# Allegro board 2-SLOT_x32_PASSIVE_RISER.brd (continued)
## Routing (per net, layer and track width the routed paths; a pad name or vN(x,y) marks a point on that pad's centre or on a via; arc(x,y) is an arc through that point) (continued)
PE_CPU1_1C_RX_11_DP: length 65.7
  TOP w0.13: J1.178 46.53,3.99 46.28,4.24 46.28,4.85 46.96,8.23 49.09,10.36 50.82,10.7 52.53,12.41 55.35,12.97 55.99,13.61 55.99,14.55 55.05,16.43 55.05,19.1 55.99,20.98 55.99,21.58 56.47,22.06 67.21,24.2 68.55,25.54 85.49,28.93 87.91,31.35 88,32.31 88,32.54 v1(88.35,32.88)
  BOTTOM w0.13: J4.A35 87.51,36.18 87.57,36.01 87.78,35.91 87.99,35.7 87.99,33.24 v1(88.35,32.88)
PE_CPU1_1C_TX_8_DN: length 70.3
  L6 w0.135: v1(38.13,6.99) 38.5,6.62 38.97,6.62 39.19,6.84 39.65,9.11 43.54,13 43.7,13.8 43.7,14.49 42.77,16.34 42.77,19.19 43.7,21.04 43.7,21.73 44.94,22.97 53.01,24.59 54.01,25.59 65.27,27.84 66.6,29.17 75.83,31.02 76.12,31.3 76.12,31.51 76.41,31.79 76.61,31.79 77.7,32.88 77.7,35.27 76.7,36.27 76.7,40.05 76.95,40.3 77.16,40.4 77.22,40.58 J4.B46
  BOTTOM w0.13: J1.193 40.13,3.99 39.88,4.24 39.88,4.66 39.5,5.04 39.5,6.44 39.14,6.8 38.32,6.8 v1(38.13,6.99)
PE_CPU1_1C_TX_8_DP: length 70.4
  L6 w0.135: v1(38.13,5.97) 38.5,6.34 39.09,6.34 39.45,6.7 39.9,8.97 43.8,12.86 43.98,13.77 43.98,14.55 43.05,16.41 43.05,19.12 43.98,20.98 43.98,21.61 45.08,22.72 53.15,24.33 54.15,25.33 65.4,27.58 66.74,28.91 75.97,30.76 77.98,32.77 77.98,35.39 76.98,36.39 76.98,39.94 77.11,40.07 77.28,40.15 77.46,40.09 J4.B45
  BOTTOM w0.13: J1.195 39.33,3.99 39.58,4.24 39.58,4.53 39.19,4.92 39.19,5.3 39.02,5.47 39.02,5.86 39.19,6.04 39.19,6.31 39.01,6.49 38.27,6.49 38.13,6.35 v1(38.13,5.97)
PE_CPU1_1C_TX_9_DN: length 71.5
  L6 w0.135: v1(40.53,6.99) 40.9,6.62 41.37,6.62 41.59,6.84 41.97,8.72 46.14,12.89 47.1,13.08 47.7,13.68 47.7,14.49 46.77,16.34 46.77,19.19 47.71,21.05 47.71,21.72 48.42,22.43 53.72,23.49 54.7,24.47 54.78,24.49 65.87,26.71 67.21,28.05 79.36,30.48 79.65,30.76 79.65,30.97 79.93,31.26 80.14,31.26 81.7,32.82 81.7,35.27 80.7,36.27 80.7,40.03 80.95,40.28 81.16,40.39 81.22,40.57 J4.B42
  BOTTOM w0.13: v1(40.53,6.99) 40.72,6.8 41.54,6.8 41.9,6.44 41.9,5.04 42.28,4.66 42.28,4.24 42.53,3.99 J1.187
PE_CPU1_1C_TX_9_DP: length 71.5
  L6 w0.135: v1(40.53,5.97) 40.9,6.34 41.49,6.34 41.85,6.7 42.23,8.58 46.27,12.63 47.24,12.82 47.98,13.56 47.98,14.55 47.05,16.41 47.05,19.12 47.99,20.99 47.99,21.6 48.55,22.17 53.85,23.23 54.84,24.21 66.01,26.45 67.35,27.79 79.5,30.22 81.98,32.7 81.98,35.39 80.98,36.39 80.98,39.92 81.12,40.05 81.29,40.14 81.47,40.08 J4.B41
  BOTTOM w0.13: v1(40.53,5.97) 40.53,6.35 40.67,6.49 41.41,6.49 41.59,6.31 41.59,6.04 41.42,5.86 41.42,5.47 41.59,5.3 41.59,4.92 41.98,4.53 41.98,4.24 41.73,3.99 J1.189
PE_CPU1_1C_TX_10_DN: length 72.7
  L6 w0.135: J4.B38 85.22,40.57 85.16,40.39 84.95,40.29 84.7,40.04 84.7,36.27 85.7,35.27 85.7,33.01 83.34,30.65 83.14,30.65 82.85,30.37 82.85,30.16 82.57,29.88 67.82,26.93 66.46,25.56 65.49,25.41 55.36,23.38 54.51,22.54 52.13,22.06 51.7,21.63 51.7,21.04 50.77,19.19 50.77,16.34 51.7,14.49 51.7,13.74 50.42,12.46 47.8,11.94 44.32,8.45 43.99,6.84 43.77,6.62 43.3,6.62 v1(42.93,6.99)
  BOTTOM w0.13: J1.181 44.93,3.99 44.68,4.24 44.68,4.66 44.3,5.04 44.3,6.44 43.94,6.8 43.12,6.8 v1(42.93,6.99)
PE_CPU1_1C_TX_10_DP: length 72.7
  L6 w0.135: v1(42.93,5.97) 43.3,6.34 43.89,6.34 44.25,6.7 44.57,8.31 47.94,11.68 50.56,12.21 51.98,13.63 51.98,14.55 51.05,16.41 51.05,19.12 51.98,20.98 51.98,21.51 52.27,21.8 54.65,22.28 55.49,23.12 65.54,25.13 66.59,25.3 67.96,26.67 82.7,29.62 85.98,32.89 85.98,35.39 84.98,36.39 84.98,39.92 85.12,40.06 85.29,40.14 85.47,40.08 J4.B37
  BOTTOM w0.13: J1.183 44.13,3.99 44.38,4.24 44.38,4.53 43.99,4.92 43.99,5.3 43.82,5.47 43.82,5.86 43.99,6.04 43.99,6.31 43.81,6.49 43.07,6.49 42.93,6.35 v1(42.93,5.97)
PE_CPU1_1C_TX_11_DN: length 76
  L6 w0.135: J4.B34 89.22,40.58 89.4,40.52 89.63,40.64 90.39,40.64 90.98,40.05 90.98,36.27 89.98,35.27 89.98,32.45 86.71,29.17 84.47,28.73 68.5,25.53 67.16,24.19 56.47,22.06 55.99,21.58 55.99,20.99 55.05,19.12 55.05,16.41 55.98,14.55 55.98,13.64 55.3,12.96 52.53,12.41 50.82,10.7 49.04,10.35 46.96,8.27 46.65,6.7 46.29,6.34 45.7,6.34 v1(45.33,5.97)
  BOTTOM w0.13: v1(45.33,5.97) 45.33,6.35 45.47,6.49 46.21,6.49 46.39,6.31 46.39,6.04 46.22,5.86 46.22,5.47 46.39,5.3 46.39,4.92 46.78,4.53 46.78,4.24 46.53,3.99 J1.177
PE_CPU1_1C_TX_11_DP: length 76
  L6 w0.135: v1(45.33,6.99) 45.7,6.62 46.17,6.62 46.39,6.84 46.71,8.41 46.99,8.69 46.99,8.9 47.28,9.18 47.48,9.18 47.77,9.47 47.77,9.67 48.05,9.96 48.26,9.96 48.9,10.6 49.3,10.68 49.41,10.85 49.81,10.93 49.98,10.82 50.69,10.96 50.97,11.25 50.97,11.45 51.26,11.74 51.46,11.74 52.39,12.66 55.17,13.22 55.7,13.76 55.7,14.49 54.77,16.34 54.77,19.19 55.71,21.06 55.71,21.69 56.33,22.31 67.03,24.45 68.36,25.79 84.42,29 84.53,29.17 84.93,29.25 85.1,29.14 85.49,29.22 85.61,29.39 86,29.47 86.17,29.35 86.57,29.43 86.85,29.72 86.85,29.92 87.14,30.21 87.34,30.21 87.63,30.49 87.63,30.7 87.91,30.98 88.12,30.98 88.4,31.27 88.4,31.47 88.69,31.76 88.9,31.76 89.7,32.56 89.7,35.39 90.7,36.39 90.7,39.93 90.27,40.36 89.7,40.36 89.52,40.27 89.52,40.27 89.46,40.09 J4.B33
  BOTTOM w0.13: v1(45.33,6.99) 45.52,6.8 46.34,6.8 46.7,6.44 46.7,5.04 47.08,4.66 47.08,4.24 47.33,3.99 J1.175
PE_CPU1_1D_RX_12_DN: length 72.5
  TOP w0.13: J1.174 48.13,3.99 48.38,4.24 48.38,4.88 49.17,8.87 49.84,9.53 51.25,9.81 53.03,11.59 60.75,13.13 63.75,12.53 66.93,13.17 70.2,12.52 73.37,13.15 76.64,12.5 79.82,13.13 83.09,12.48 84.72,12.8 85.69,13.77 85.69,14.55 86.63,16.43 86.63,19.11 85.69,20.98 85.69,21.93 93.23,29.47 93.69,31.73 93.69,32.53 v1(93.33,32.88)
  BOTTOM w0.13: v1(93.33,32.88) 93.69,33.24 93.69,33.68 93.51,33.85 93.51,34.24 93.69,34.42 93.69,35.57 93.6,35.66 93.44,35.74 93.26,35.68 J4.A30
PE_CPU1_1D_RX_12_DP: length 72.5
  TOP w0.13: v1(94.35,32.88) 93.99,32.53 93.99,31.7 93.52,29.32 85.99,21.8 85.99,21.06 86.93,19.18 86.93,16.36 85.99,14.48 85.99,13.64 84.87,12.52 83.09,12.17 79.82,12.82 76.64,12.19 73.37,12.84 70.2,12.2 66.93,12.86 63.75,12.22 60.75,12.82 53.18,11.31 51.4,9.53 49.99,9.25 49.45,8.71 48.68,4.85 48.68,4.24 48.93,3.99 J1.172
  BOTTOM w0.13: v1(94.35,32.88) 93.99,33.24 93.99,35.7 93.78,35.91 93.57,36.01 93.51,36.18 J4.A29
PE_CPU1_1D_RX_13_DN: length 72.9
  TOP w0.13: v1(97.33,32.88) 97.7,32.51 97.7,32.33 97.6,31.84 87.69,21.93 87.69,20.98 88.63,19.11 88.63,16.43 87.69,14.55 87.69,13.77 85.69,11.77 83.08,11.25 79.81,11.9 76.63,11.27 73.36,11.92 70.19,11.28 66.92,11.94 63.74,11.3 60.75,11.9 53.64,10.48 51.46,8.3 50.78,4.88 50.78,4.24 50.53,3.99 J1.168
  BOTTOM w0.13: J4.A26 97.26,35.68 97.44,35.74 97.6,35.66 97.69,35.57 97.69,34.42 97.51,34.24 97.51,33.85 97.69,33.68 97.69,33.24 v1(97.33,32.88)
PE_CPU1_1D_RX_13_DP: length 72.9
  TOP w0.13: v1(98.35,32.88) 98,32.54 98,32.3 97.88,31.69 87.99,21.8 87.99,21.06 88.93,19.18 88.93,16.36 87.99,14.48 87.99,13.64 85.84,11.49 83.08,10.94 79.81,11.59 76.63,10.96 73.36,11.61 70.19,10.97 66.92,11.63 63.74,10.99 60.75,11.59 53.79,10.2 51.74,8.15 51.08,4.85 51.08,4.24 51.33,3.99 J1.166
  BOTTOM w0.13: v1(98.35,32.88) 97.99,33.24 97.99,35.7 97.78,35.91 97.57,36.01 97.51,36.18 J4.A25
PE_CPU1_1D_RX_14_DN: length 74.5
  TOP w0.13: v1(101.33,32.88) 101.7,32.52 101.7,32.13 101.58,31.55 98.06,28.03 95.23,27.47 89.69,21.93 89.69,20.98 90.63,19.11 90.63,16.43 89.69,14.55 89.69,13.77 86.6,10.68 83.17,10 79.9,10.65 76.72,10.02 73.45,10.67 70.28,10.04 67.01,10.69 63.83,10.05 60.75,10.67 55.06,9.53 53.87,8.34 53.18,4.88 53.18,4.24 52.93,3.99 J1.162
  BOTTOM w0.13: J4.A22 101.26,35.68 101.44,35.74 101.6,35.66 101.69,35.57 101.69,34.42 101.51,34.24 101.51,33.85 101.69,33.68 101.69,33.24 v1(101.33,32.88)
PE_CPU1_1D_RX_14_DP: length 74.5
  TOP w0.13: v1(102.35,32.88) 102,32.53 102,32.1 101.86,31.4 98.21,27.75 95.38,27.18 89.99,21.8 89.99,21.06 90.93,19.18 90.93,16.36 89.99,14.48 89.99,13.64 86.75,10.4 83.17,9.69 79.9,10.34 76.72,9.71 73.45,10.36 70.28,9.72 67.01,10.38 63.83,9.74 60.75,10.36 55.21,9.25 54.15,8.19 53.48,4.85 53.48,4.24 53.73,3.99 J1.160
  BOTTOM w0.13: J4.A21 101.52,36.18 101.57,36.01 101.78,35.91 101.99,35.7 101.99,33.24 v1(102.35,32.88)
PE_CPU1_1D_RX_15_DN: length 75.7
  TOP w0.13: v1(105.33,32.88) 105.69,32.53 105.69,32.08 105.4,31.79 103.49,31.41 99.01,26.92 96.16,26.35 91.69,21.88 91.69,20.98 92.63,19.1 92.63,16.43 91.69,14.55 91.69,13.74 87.6,9.66 83.16,8.77 79.89,9.42 76.72,8.79 73.44,9.44 70.27,8.8 67,9.46 63.82,8.82 60.75,9.44 56.76,8.64 56.22,8.1 55.58,4.88 55.58,4.24 55.33,3.99 J1.156
  BOTTOM w0.13: v1(105.33,32.88) 105.69,33.24 105.69,35.68 105.9,35.9 106.11,36 106.17,36.18 J4.A17
PE_CPU1_1D_RX_15_DP: length 75.7
  TOP w0.13: v1(106.35,32.88) 105.99,32.53 105.99,31.95 105.55,31.51 103.64,31.13 99.16,26.64 96.32,26.07 91.99,21.75 91.99,21.05 92.93,19.17 92.93,16.36 91.99,14.48 91.99,13.62 87.75,9.37 83.16,8.46 79.89,9.11 76.72,8.47 73.44,9.13 70.27,8.49 67,9.15 63.82,8.51 60.75,9.13 56.91,8.36 56.5,7.95 55.88,4.85 55.88,4.24 56.13,3.99 J1.154
  BOTTOM w0.13: J4.A16 106.42,35.67 106.25,35.73 106.08,35.65 105.99,35.56 105.99,34.42 106.17,34.24 106.17,33.85 105.99,33.68 105.99,33.24 v1(106.35,32.88)
PE_CPU1_1D_TX_12_DN: length 80.9
  L6 w0.135: v1(47.73,6.99) 48.1,6.62 48.57,6.62 48.79,6.84 49.2,8.9 49.8,9.5 51.26,9.79 53.04,11.57 60.75,13.11 63.75,12.51 66.92,13.14 70.19,12.49 73.37,13.12 76.64,12.47 79.81,13.11 83.08,12.45 84.72,12.78 85.7,13.76 85.7,14.55 86.63,16.41 86.63,19.12 85.71,20.95 85.71,21.91 93.84,30.04 93.84,30.24 94.13,30.53 94.33,30.53 95.7,31.9 95.7,35.27 94.7,36.27 94.7,40.05 94.95,40.3 95.16,40.4 95.22,40.58 J4.B28
  BOTTOM w0.13: J1.169 49.73,3.99 49.48,4.24 49.48,4.66 49.1,5.04 49.1,6.44 48.74,6.8 47.92,6.8 v1(47.73,6.99)
PE_CPU1_1D_TX_12_DP: length 80.9
  L6 w0.135: J4.B27 95.46,40.09 95.28,40.15 95.11,40.07 94.98,39.94 94.98,36.39 95.98,35.39 95.98,31.78 85.99,21.79 85.99,21.01 86.91,19.19 86.91,16.34 85.98,14.49 85.98,13.64 84.86,12.52 83.08,12.17 79.81,12.82 76.64,12.19 73.37,12.84 70.19,12.2 66.92,12.86 63.75,12.22 60.75,12.82 53.18,11.31 51.4,9.53 49.94,9.24 49.46,8.76 49.05,6.7 48.69,6.34 48.1,6.34 v1(47.73,5.97)
  BOTTOM w0.13: J1.171 48.93,3.99 49.18,4.24 49.18,4.53 48.79,4.92 48.79,5.3 48.62,5.47 48.62,5.86 48.79,6.04 48.79,6.31 48.61,6.49 47.87,6.49 47.73,6.35 v1(47.73,5.97)
PE_CPU1_1D_TX_13_DN: length 81.7
  L6 w0.135: v1(50.13,6.99) 50.5,6.62 50.97,6.62 51.19,6.84 51.49,8.33 53.61,10.45 60.82,11.89 63.81,11.29 66.92,11.91 70.19,11.26 73.36,11.89 76.63,11.24 79.81,11.87 83.08,11.22 85.73,11.75 87.7,13.72 87.7,14.55 88.63,16.41 88.63,19.12 87.7,20.98 87.7,21.85 95.95,30.1 97.28,30.37 98.46,31.54 98.46,31.75 98.74,32.03 98.95,32.03 99.7,32.79 99.7,35.27 98.7,36.27 98.7,40.05 98.94,40.3 99.16,40.4 99.22,40.58 J4.B24
  BOTTOM w0.13: J1.163 52.13,3.99 51.88,4.24 51.88,4.66 51.5,5.04 51.5,6.44 51.14,6.8 50.32,6.8 v1(50.13,6.99)
PE_CPU1_1D_TX_13_DP: length 81.7
  L6 w0.135: v1(50.13,5.97) 50.5,6.34 51.09,6.34 51.45,6.7 51.75,8.19 53.75,10.19 60.82,11.6 63.81,11.01 66.92,11.63 70.19,10.97 73.36,11.61 76.63,10.96 79.81,11.59 83.08,10.94 85.87,11.49 87.98,13.6 87.98,14.49 88.91,16.34 88.91,19.19 87.98,21.04 87.98,21.74 96.09,29.84 97.42,30.11 99.98,32.67 99.98,35.39 98.98,36.39 98.98,39.94 99.11,40.07 99.28,40.15 99.46,40.09 J4.B23
  BOTTOM w0.13: J1.165 51.33,3.99 51.58,4.24 51.58,4.53 51.19,4.92 51.19,5.3 51.02,5.47 51.02,5.86 51.19,6.04 51.19,6.31 51.01,6.49 50.27,6.49 50.13,6.35 v1(50.13,5.97)
PE_CPU1_1D_TX_14_DN: length 83.1
  L6 w0.135: J4.B20 103.22,40.58 103.16,40.4 102.95,40.3 102.7,40.05 102.7,36.27 103.7,35.27 103.7,32.85 102.47,31.62 102.26,31.62 101.98,31.33 101.98,31.13 100.68,29.83 96.92,29.07 89.7,21.85 89.7,20.98 90.63,19.12 90.63,16.41 89.7,14.55 89.7,13.72 86.65,10.67 83.23,9.98 79.96,10.64 76.79,10 73.52,10.66 70.34,10.02 67.07,10.68 63.9,10.04 60.82,10.66 55.09,9.51 53.89,8.31 53.59,6.84 53.37,6.62 52.9,6.62 v1(52.53,6.99)
  BOTTOM w0.13: J1.157 54.53,3.99 54.28,4.24 54.28,4.66 53.9,5.04 53.9,6.44 53.54,6.8 52.72,6.8 v1(52.53,6.99)
PE_CPU1_1D_TX_14_DP: length 83.2
  L6 w0.135: J4.B19 103.46,40.09 103.28,40.15 103.11,40.07 102.98,39.94 102.98,36.39 103.98,35.39 103.98,32.73 100.82,29.57 97.06,28.82 89.98,21.74 89.98,21.04 90.91,19.19 90.91,16.34 89.98,14.49 89.98,13.6 86.79,10.41 83.23,9.7 79.96,10.35 76.79,9.72 73.52,10.37 70.34,9.74 67.07,10.39 63.9,9.76 60.82,10.37 55.23,9.25 54.14,8.17 53.85,6.7 53.49,6.34 52.9,6.34 v1(52.53,5.97)
  BOTTOM w0.13: J1.159 53.73,3.99 53.98,4.24 53.98,4.53 53.59,4.92 53.59,5.3 53.42,5.47 53.42,5.86 53.59,6.04 53.59,6.31 53.41,6.49 52.67,6.49 52.53,6.35 v1(52.53,5.97)
PE_CPU1_1D_TX_15_DN: length 84.6
  L6 w0.135: J4.B15 108.23,40.12 108.41,40.18 108.54,40.11 108.7,39.95 108.7,36.85 107.7,34.85 107.7,33.02 106.87,32.2 106.67,32.2 106.38,31.91 106.38,31.71 106.1,31.42 105.89,31.42 105.61,31.14 105.61,30.93 105.32,30.65 105.12,30.65 104.83,30.36 104.83,30.16 104.55,29.87 104.34,29.87 104.06,29.59 104.06,29.38 103.83,29.16 97.8,27.95 91.7,21.85 91.7,20.98 92.63,19.12 92.63,16.41 91.7,14.55 91.7,13.72 87.61,9.63 83.22,8.75 79.95,9.41 76.78,8.77 73.51,9.43 70.34,8.79 67.06,9.45 63.89,8.81 60.77,9.44 58.9,9.06 58.73,9.17 58.33,9.1 58.22,8.93 57.82,8.85 57.65,8.96 57.26,8.88 57.14,8.71 56.75,8.63 56.25,8.14 55.99,6.84 55.77,6.62 55.3,6.62 v1(54.93,6.99)
  BOTTOM w0.13: J1.151 56.93,3.99 56.68,4.24 56.68,4.66 56.3,5.04 56.3,6.44 55.94,6.8 55.12,6.8 v1(54.93,6.99)
PE_CPU1_1D_TX_15_DP: length 84.6
  L6 w0.135: v1(54.93,5.97) 55.3,6.34 55.89,6.34 56.25,6.7 56.51,8 56.88,8.37 60.77,9.15 63.89,8.53 67.06,9.16 70.34,8.51 73.51,9.14 76.78,8.49 79.95,9.12 83.22,8.47 87.75,9.37 91.98,13.6 91.98,14.49 92.91,16.34 92.91,19.19 91.98,21.04 91.98,21.74 97.94,27.69 103.97,28.9 107.98,32.91 107.98,34.79 108.98,36.78 108.98,40.07 108.71,40.34 108.54,40.43 108.48,40.61 J4.B14
  BOTTOM w0.13: v1(54.93,5.97) 54.93,6.35 55.07,6.49 55.81,6.49 55.99,6.31 55.99,6.04 55.82,5.86 55.82,5.47 55.99,5.3 55.99,4.92 56.38,4.53 56.38,4.24 56.13,3.99 J1.153
PE_CPU1_2A_RX_0_DN: length 28.2
  TOP w0.13: v1(57.33,5.97) 57.33,6.35 57.47,6.49 57.82,6.49 57.98,6.34 57.98,5.66 57.8,5.48 57.8,5.09 57.98,4.92 57.98,4.24 57.73,3.99 J1.150
  L3 w0.135: J3.A81 42.2,15.79 42.14,15.61 41.93,15.5 41.7,15.27 41.7,13.66 46.06,9.3 49.5,8.61 51.63,9.04 52.65,9.24 55.51,8.67 55.77,8.4 55.89,7.8 55.89,6.63 56.18,6.34 56.96,6.34 v1(57.33,5.97)
PE_CPU1_2A_RX_0_DP: length 28.2
  TOP w0.13: v1(57.33,6.99) 57.52,6.8 57.95,6.8 58.28,6.47 58.28,4.24 58.53,3.99 J1.148
  L3 w0.135: v1(57.33,6.99) 56.96,6.62 56.3,6.62 56.17,6.74 56.17,7.83 56.03,8.54 55.64,8.93 55.25,9.01 55.13,9.18 54.74,9.26 54.57,9.14 52.65,9.53 52.25,9.45 52.08,9.56 51.69,9.48 51.57,9.31 49.5,8.9 46.19,9.56 45.08,10.67 45.08,10.88 44.8,11.16 44.59,11.16 44.31,11.45 44.31,11.65 44.02,11.94 43.82,11.94 43.53,12.22 43.53,12.43 43.24,12.71 43.04,12.71 42.75,13 42.75,13.2 42.47,13.49 42.26,13.49 41.98,13.77 41.98,15.15 42.1,15.27 42.27,15.36 42.45,15.3 J3.A80
PE_CPU1_2A_RX_1_DN: length 27.2
  TOP w0.13: J1.144 60.13,3.99 60.38,4.24 60.38,4.92 60.2,5.09 60.2,5.48 60.38,5.66 60.38,6.34 60.22,6.49 59.87,6.49 59.73,6.35 v1(59.73,5.97)
  L3 w0.135: v1(59.73,5.97) 59.36,6.34 58.58,6.34 58.29,6.63 58.29,7.8 58.21,8.21 57.5,8.93 56.8,9.62 52.55,10.47 50.64,10.09 49.32,9.82 48,10.09 46.25,11.84 45.9,12.19 45.7,13.21 45.7,15.27 45.93,15.5 46.14,15.61 46.2,15.79 J3.A77
PE_CPU1_2A_RX_1_DP: length 27.2
  TOP w0.13: v1(59.73,6.99) 59.92,6.8 60.35,6.8 60.68,6.47 60.68,4.24 60.93,3.99 J1.142
  L3 w0.135: J3.A76 46.45,15.3 46.27,15.36 46.1,15.27 45.98,15.16 45.98,13.24 46.16,12.32 46.45,12.04 46.65,12.04 46.94,11.75 46.94,11.55 47.22,11.26 47.43,11.26 47.71,10.98 47.71,10.77 48.14,10.35 49.32,10.11 49.9,10.23 50.01,10.4 50.41,10.47 50.58,10.36 52.55,10.76 54.68,10.33 54.85,10.44 55.24,10.36 55.36,10.19 55.75,10.11 55.93,10.23 56.32,10.15 56.43,9.98 56.94,9.88 57.69,9.12 57.9,9.12 58.18,8.84 58.18,8.63 58.47,8.35 58.57,7.83 58.57,6.74 58.7,6.62 59.36,6.62 v1(59.73,6.99)
PE_CPU1_2A_RX_2_DN: length 24.7
  TOP w0.13: v1(62.13,5.97) 62.13,6.35 62.27,6.49 62.62,6.49 62.78,6.34 62.78,5.66 62.6,5.48 62.6,5.09 62.78,4.92 62.78,4.24 62.53,3.99 J1.138
  L3 w0.135: J3.A73 50.2,15.79 50.14,15.61 49.93,15.51 49.7,15.28 49.7,13.66 51.29,12.07 58.59,10.61 60.57,8.63 60.69,8.03 60.69,6.63 60.98,6.34 61.76,6.34 v1(62.13,5.97)
PE_CPU1_2A_RX_2_DP: length 24.7
  TOP w0.13: J1.136 63.33,3.99 63.08,4.24 63.08,6.47 62.75,6.8 62.32,6.8 v1(62.13,6.99)
  L3 w0.135: v1(62.13,6.99) 61.76,6.62 61.1,6.62 60.97,6.74 60.97,8.06 60.96,8.15 60.83,8.77 60.28,9.32 60.28,9.52 60,9.81 59.79,9.81 59.51,10.09 59.51,10.3 59.22,10.58 59.01,10.58 58.73,10.87 58.33,10.95 58.22,11.12 57.82,11.2 57.65,11.08 53.58,11.9 53.46,12.07 53.07,12.15 52.9,12.03 52.5,12.11 52.39,12.28 51.99,12.36 51.82,12.25 51.43,12.33 50.75,13 50.75,13.2 50.47,13.49 50.26,13.49 49.98,13.78 49.98,15.16 50.09,15.28 50.27,15.36 50.45,15.3 J3.A72
PE_CPU1_2A_RX_3_DN: length 23.3
  TOP w0.13: J1.132 64.93,3.99 65.18,4.24 65.18,4.92 65,5.09 65,5.48 65.18,5.66 65.18,6.34 65.02,6.49 64.67,6.49 64.53,6.35 v1(64.53,5.97)
  L3 w0.135: v1(64.53,5.97) 64.16,6.34 63.38,6.34 63.09,6.63 63.09,7.8 62.85,9.02 60.54,11.32 54.99,12.44 53.7,13.72 53.7,15.28 53.93,15.51 54.14,15.61 54.2,15.79 J3.A69
PE_CPU1_2A_RX_3_DP: length 23.3
  TOP w0.13: v1(64.53,6.99) 64.72,6.8 65.15,6.8 65.48,6.47 65.48,4.24 65.73,3.99 J1.130
  L3 w0.135: J3.A68 54.45,15.3 54.27,15.36 54.09,15.28 53.98,15.16 53.98,13.84 54.26,13.55 54.47,13.55 54.75,13.27 54.75,13.06 55.12,12.69 55.52,12.61 55.69,12.73 56.09,12.65 56.2,12.48 56.6,12.4 56.77,12.51 57.16,12.43 57.28,12.26 57.67,12.18 57.84,12.3 58.24,12.22 58.35,12.05 60.68,11.58 61.56,10.71 61.76,10.71 62.05,10.42 62.05,10.22 62.33,9.93 62.54,9.93 62.82,9.65 62.82,9.44 63.11,9.16 63.37,7.83 63.37,6.74 63.5,6.62 64.16,6.62 v1(64.53,6.99)
PE_CPU1_2A_TX_0_DN: length 31.9
  BOTTOM w0.13: J1.145 59.33,3.99 59.08,4.24 59.08,4.85 58.82,6.13 58.96,6.34 58.89,6.72 58.68,6.86 58.6,7.24 58.74,7.44 58.66,7.83 58.46,7.96 58.38,8.34 58.03,8.69 54.72,9.35 51.55,8.72 47.99,9.43 45.68,11.74 45.68,11.99 45.41,12.26 45.16,12.26 44.89,12.54 44.89,12.79 44.61,13.06 44.36,13.06 44.09,13.34 43.99,13.82 43.99,14.55 42.99,16.55 42.99,19.58 43.47,20.06 44.01,20.06 44.17,19.97 44.23,19.8 J3.B79
PE_CPU1_2A_TX_0_DP: length 31.9
  BOTTOM w0.13: J3.B78 44.48,20.3 44.31,20.25 44.08,20.36 43.35,20.36 42.69,19.7 42.69,16.48 43.69,14.48 43.69,13.79 43.81,13.19 47.84,9.15 51.55,8.41 54.72,9.04 57.88,8.41 58.1,8.19 58.78,4.82 58.78,4.24 58.53,3.99 J1.147
PE_CPU1_2A_TX_1_DN: length 30.9
  BOTTOM w0.13: J1.139 61.73,3.99 61.48,4.24 61.48,5.16 61.21,6.49 61.35,6.69 61.27,7.07 61.07,7.21 60.99,7.59 61.13,7.8 61.05,8.18 60.85,8.32 60.77,8.7 59.9,9.57 54.78,10.59 51.64,9.96 50.51,10.19 49.87,10.83 49.87,11.08 49.59,11.35 49.34,11.35 49.07,11.63 49.07,11.88 48.8,12.15 48.55,12.15 48.27,12.43 47.99,13.83 47.99,14.55 46.99,16.55 46.99,19.57 47.47,20.04 48,20.04 48.17,19.96 48.22,19.79 J3.B75
PE_CPU1_2A_TX_1_DP: length 30.9
  BOTTOM w0.13: J1.141 60.93,3.99 61.18,4.24 61.18,5.12 60.49,8.55 59.75,9.28 54.78,10.28 51.64,9.65 50.36,9.91 47.99,12.28 47.69,13.8 47.69,14.48 46.69,16.48 46.69,19.7 47.34,20.35 48.07,20.35 48.3,20.24 48.48,20.29 J3.B74
PE_CPU1_2A_TX_2_DN: length 28.5
  BOTTOM w0.13: J1.133 64.13,3.99 63.88,4.24 63.88,5.34 63.63,6.61 63.76,6.82 63.69,7.2 63.48,7.34 63.4,7.72 63.54,7.93 63.47,8.31 63.26,8.44 63.18,8.83 61.54,10.46 55.59,11.66 55.45,11.86 55.07,11.94 54.87,11.8 54.48,11.88 54.35,12.08 53.97,12.16 53.76,12.02 53.38,12.1 52.08,13.4 51.99,13.82 51.99,14.55 50.99,16.55 50.99,19.58 51.47,20.06 52.01,20.06 52.17,19.97 52.23,19.8 J3.B71
PE_CPU1_2A_TX_2_DP: length 28.5
  BOTTOM w0.13: J3.B70 52.48,20.3 52.31,20.25 52.08,20.36 51.35,20.36 50.69,19.7 50.69,16.48 51.69,14.48 51.69,13.79 51.79,13.25 53.23,11.82 61.39,10.18 62.9,8.68 63.58,5.31 63.58,4.24 63.33,3.99 J1.135
PE_CPU1_2A_TX_3_DN: length 27.1
  BOTTOM w0.13: J1.127 66.53,3.99 66.28,4.24 66.28,5.34 65.99,6.79 66.13,7 66.05,7.38 65.84,7.52 65.77,7.9 65.91,8.1 65.83,8.49 65.62,8.62 65.55,9 63.2,11.36 59.01,12.19 58.88,12.4 58.49,12.47 58.29,12.34 57.91,12.41 57.77,12.62 57.39,12.7 57.18,12.56 56.8,12.63 56.09,13.35 55.99,13.82 55.99,14.55 54.99,16.55 54.99,19.58 55.47,20.06 56.01,20.06 56.17,19.97 56.23,19.8 J3.B67
PE_CPU1_2A_TX_3_DP: length 27.1
  BOTTOM w0.13: J3.B66 56.48,20.3 56.31,20.25 56.08,20.36 55.34,20.36 54.69,19.7 54.69,16.48 55.69,14.48 55.69,13.79 55.81,13.2 56.65,12.35 63.05,11.07 65.27,8.85 65.98,5.31 65.98,4.24 65.73,3.99 J1.129
PE_CPU1_2B_RX_4_DN: length 21.9
  TOP w0.13: v1(66.93,5.97) 66.93,6.35 67.07,6.49 67.42,6.49 67.58,6.34 67.58,5.66 67.4,5.48 67.4,5.09 67.58,4.92 67.58,4.24 67.33,3.99 J1.126
  L3 w0.135: v1(66.93,5.97) 66.56,6.34 65.78,6.34 65.49,6.63 65.49,7.8 65.25,9.03 62.03,12.25 58.38,12.98 57.7,13.66 57.7,15.27 57.93,15.5 58.14,15.61 58.2,15.79 J3.A65
PE_CPU1_2B_RX_4_DP: length 21.9
  TOP w0.13: J1.124 68.13,3.99 67.88,4.24 67.88,6.47 67.55,6.8 67.12,6.8 v1(66.93,6.99)
  L3 w0.135: v1(66.93,6.99) 66.56,6.62 65.9,6.62 65.77,6.74 65.77,7.83 65.5,9.17 65.22,9.46 65.22,9.66 64.93,9.95 64.73,9.95 64.44,10.23 64.44,10.44 64.16,10.72 63.95,10.72 63.67,11.01 63.67,11.21 63.38,11.5 63.18,11.5 62.17,12.51 61.74,12.59 61.63,12.77 61.23,12.84 61.06,12.73 60.67,12.81 60.55,12.98 60.16,13.06 59.99,12.95 59.59,13.02 59.48,13.2 59.08,13.27 58.91,13.16 58.51,13.24 57.98,13.78 57.98,15.15 58.1,15.27 58.27,15.36 58.45,15.3 J3.A64
PE_CPU1_2B_RX_5_DN: length 20.5
  TOP w0.13: J1.120 69.73,3.99 69.98,4.24 69.98,4.92 69.8,5.09 69.8,5.48 69.98,5.66 69.98,6.34 69.82,6.49 69.47,6.49 69.33,6.35 v1(69.33,5.97)
  L3 w0.135: v1(69.33,5.97) 68.96,6.34 68.18,6.34 67.89,6.63 67.89,7.39 67.48,9.47 64.13,12.82 62.22,13.2 61.7,13.72 61.7,15.27 61.93,15.5 62.14,15.61 62.2,15.79 J3.A61
PE_CPU1_2B_RX_5_DP: length 20.5
  TOP w0.13: J1.118 70.53,3.99 70.28,4.24 70.28,6.47 69.95,6.8 69.52,6.8 v1(69.33,6.99)
  L3 w0.135: J3.A60 62.45,15.3 62.27,15.36 62.1,15.28 61.98,15.16 61.98,13.84 62.36,13.46 62.76,13.38 62.93,13.49 63.32,13.41 63.44,13.24 64.26,13.08 64.63,12.71 64.84,12.71 65.12,12.43 65.12,12.22 65.41,11.94 65.61,11.94 65.9,11.65 65.9,11.45 66.18,11.16 66.39,11.16 66.67,10.87 66.67,10.67 66.96,10.38 67.16,10.38 67.45,10.1 67.45,9.89 67.73,9.61 67.96,8.49 68.13,8.38 68.21,7.98 68.09,7.81 68.17,7.42 68.17,6.74 68.3,6.62 68.96,6.62 v1(69.33,6.99)
PE_CPU1_2B_RX_6_DN: length 19.1
  TOP w0.13: J1.114 72.13,3.99 72.38,4.24 72.38,4.92 72.2,5.09 72.2,5.48 72.38,5.66 72.38,6.34 72.22,6.49 71.87,6.49 71.73,6.35 v1(71.73,5.97)
  L3 w0.135: v1(71.73,5.97) 71.36,6.34 70.58,6.34 70.29,6.63 70.29,7.8 69.96,9.49 65.7,13.74 65.7,15.27 65.93,15.5 66.14,15.61 66.2,15.79 J3.A57
PE_CPU1_2B_RX_6_DP: length 19
  TOP w0.13: v1(71.73,6.99) 71.92,6.8 72.35,6.8 72.68,6.47 72.68,4.24 72.93,3.99 J1.112
  L3 w0.135: J3.A56 66.45,15.3 66.27,15.36 66.1,15.27 65.98,15.16 65.98,13.86 66.26,13.58 66.47,13.58 66.76,13.29 66.76,13.08 67.04,12.8 67.25,12.8 67.53,12.51 67.53,12.31 67.82,12.02 68.02,12.02 68.31,11.74 68.31,11.53 68.59,11.25 68.8,11.25 69.08,10.96 69.08,10.76 69.37,10.47 69.57,10.47 69.86,10.19 69.86,9.98 70.21,9.63 70.36,8.91 70.53,8.79 70.61,8.4 70.49,8.23 70.57,7.83 70.57,6.74 70.7,6.62 71.36,6.62 v1(71.73,6.99)
PE_CPU1_2B_RX_7_DN: length 18.3
  TOP w0.13: J1.108 74.53,3.99 74.78,4.24 74.78,4.92 74.6,5.09 74.6,5.48 74.78,5.66 74.78,6.34 74.62,6.49 74.27,6.49 74.13,6.35 v1(74.13,5.97)
  L3 w0.135: J3.A53 70.16,15.87 70.1,15.69 69.89,15.58 69.7,15.39 69.7,13.84 70.08,11.93 70.92,11.1 70.92,11.1 72.31,9.71 72.69,7.77 72.69,6.57 73,6.26 73.84,6.26 v1(74.13,5.97)
PE_CPU1_2B_RX_7_DP: length 18.3
  TOP w0.13: J1.106 75.33,3.99 75.08,4.24 75.08,6.47 74.75,6.8 74.32,6.8 v1(74.13,6.99)
  L3 w0.135: v1(74.13,6.99) 73.68,6.54 73.12,6.54 72.97,6.69 72.97,7.8 72.78,8.77 72.89,8.94 72.81,9.34 72.64,9.45 72.56,9.85 71.89,10.52 71.89,10.72 71.6,11.01 71.4,11.01 71.11,11.29 71.11,11.5 70.83,11.79 70.62,11.79 70.34,12.07 70.19,12.79 70.31,12.96 70.23,13.36 70.06,13.47 69.98,13.87 69.98,15.28 70.06,15.35 70.23,15.44 70.41,15.38 J3.A52
PE_CPU1_2B_TX_4_DN: length 25.7
  BOTTOM w0.13: J1.121 68.93,3.99 68.68,4.24 68.68,5.34 68.36,6.97 68.49,7.17 68.42,7.55 68.21,7.69 68.13,8.07 68.27,8.28 68.19,8.66 67.99,8.8 67.91,9.18 64.82,12.27 62.59,12.71 62.45,12.92 62.07,13 61.86,12.86 61.48,12.94 61.34,13.14 60.96,13.22 60.75,13.08 60.37,13.16 60.06,13.47 59.99,13.82 59.99,14.55 58.99,16.55 58.99,19.57 59.47,20.05 60.01,20.05 60.17,19.97 60.23,19.79 J3.B63
PE_CPU1_2B_TX_4_DP: length 25.7
  BOTTOM w0.13: J1.123 68.13,3.99 68.38,4.24 68.38,5.31 67.63,9.03 64.67,11.99 60.22,12.88 59.78,13.32 59.69,13.79 59.69,14.48 58.69,16.48 58.69,19.7 59.34,20.35 60.08,20.35 60.31,20.24 60.48,20.3 J3.B62
PE_CPU1_2B_TX_5_DN: length 24
  BOTTOM w0.13: J1.115 71.33,3.99 71.08,4.24 71.08,5.34 70.78,6.82 70.92,7.03 70.85,7.41 70.64,7.55 70.56,7.93 70.7,8.13 70.62,8.52 70.42,8.65 70.34,9.03 67.75,11.63 67.75,11.88 67.47,12.15 67.22,12.15 66.95,12.43 66.95,12.67 66.67,12.95 66.43,12.95 66.15,13.22 64.24,13.61 63.99,13.85 63.99,14.55 62.99,16.55 62.99,19.57 63.47,20.05 64,20.05 64.17,19.96 64.23,19.79 J3.B59
PE_CPU1_2B_TX_5_DP: length 24
  BOTTOM w0.13: J3.B58 64.48,20.3 64.3,20.24 64.08,20.35 63.34,20.35 62.69,19.7 62.69,16.48 63.69,14.48 63.69,13.73 64.09,13.33 66,12.94 70.06,8.88 70.78,5.31 70.78,4.24 70.53,3.99 J1.117
PE_CPU1_2B_TX_6_DN: length 22.6
  BOTTOM w0.13: J1.109 73.73,3.99 73.48,4.24 73.48,5.34 73.26,6.44 73.4,6.64 73.32,7.03 73.12,7.16 73.04,7.54 73.18,7.75 73.1,8.13 72.89,8.27 72.82,8.65 69.67,11.79 69.67,12.04 69.4,12.32 69.15,12.32 68.88,12.59 68.88,12.84 68.6,13.11 68.35,13.11 68.08,13.39 67.99,13.82 67.99,14.55 66.99,16.55 66.99,19.57 67.47,20.04 68,20.04 68.17,19.96 68.22,19.79 J3.B55
PE_CPU1_2B_TX_6_DP: length 22.6
  BOTTOM w0.13: J1.111 72.93,3.99 73.18,4.24 73.18,5.31 72.54,8.5 67.8,13.24 67.69,13.79 67.69,14.48 66.69,16.48 66.69,19.7 67.34,20.35 68.07,20.35 68.3,20.23 68.48,20.29 J3.B54
PE_CPU1_2B_TX_7_DN: length 21.8
  BOTTOM w0.13: J3.B51 72.23,19.79 72.17,19.96 72,20.04 71.47,20.04 70.99,19.57 70.99,16.55 71.99,14.55 71.99,13.81 72.23,12.63 72.5,12.36 72.75,12.36 73.03,12.08 73.03,11.84 73.3,11.56 73.55,11.56 73.82,11.29 73.82,11.04 74.95,9.91 75.03,9.53 75.24,9.39 75.31,9.01 75.18,8.8 75.25,8.42 75.46,8.28 75.53,7.9 75.4,7.7 75.88,5.28 75.88,4.24 76.13,3.99 J1.103
PE_CPU1_2B_TX_7_DP: length 21.8
  BOTTOM w0.13: J1.105 75.33,3.99 75.58,4.24 75.58,5.25 74.67,9.76 71.95,12.48 71.69,13.78 71.69,14.48 70.69,16.48 70.69,19.7 71.34,20.35 72.08,20.35 72.3,20.24 72.48,20.29 J3.B50
PE_CPU1_2C_RX_8_DN: length 17
  TOP w0.13: v1(76.53,5.97) 76.53,6.35 76.67,6.49 77.02,6.49 77.18,6.34 77.18,5.66 77,5.48 77,5.09 77.18,4.92 77.18,4.24 76.93,3.99 J1.102
  L3 w0.135: J3.A48 75.21,15.26 75.39,15.32 75.56,15.24 75.71,15.09 75.71,13.67 75.63,13.27 74.81,9.2 75.09,7.8 75.09,6.63 75.38,6.34 76.16,6.34 v1(76.53,5.97)
PE_CPU1_2C_RX_8_DP: length 17
  TOP w0.13: v1(76.53,6.99) 76.72,6.8 77.15,6.8 77.48,6.47 77.48,4.24 77.73,3.99 J1.100
  L3 w0.135: J3.A47 75.46,15.75 75.52,15.57 75.73,15.47 75.99,15.21 75.99,13.65 75.9,13.21 76.01,13.04 75.93,12.65 75.76,12.53 75.43,10.87 75.1,9.2 75.37,7.83 75.37,6.74 75.5,6.62 76.16,6.62 v1(76.53,6.99)
PE_CPU1_2C_RX_9_DN: length 17.5
  TOP w0.13: v1(78.93,5.97) 78.93,6.35 79.07,6.49 79.42,6.49 79.58,6.34 79.58,5.66 79.4,5.48 79.4,5.09 79.58,4.92 79.58,4.24 79.33,3.99 J1.96
  L3 w0.135: J3.A44 79.21,15.26 79.39,15.32 79.56,15.24 79.7,15.1 79.7,13.78 79.34,11.97 78.07,10.7 77.49,7.83 77.49,6.63 77.78,6.34 78.56,6.34 v1(78.93,5.97)
PE_CPU1_2C_RX_9_DP: length 17.5
  TOP w0.13: J1.94 80.13,3.99 79.88,4.24 79.88,6.47 79.55,6.8 79.12,6.8 v1(78.93,6.99)
  L3 w0.135: J3.A43 79.46,15.75 79.52,15.57 79.73,15.47 79.98,15.21 79.98,13.76 79.9,13.36 80.01,13.19 79.94,12.79 79.76,12.68 79.6,11.84 78.33,10.57 77.77,7.8 77.77,6.74 77.9,6.62 78.56,6.62 v1(78.93,6.99)
PE_CPU1_2C_RX_10_DN: length 18.3
  TOP w0.13: J1.90 81.73,3.99 81.98,4.24 81.98,4.92 81.8,5.09 81.8,5.48 81.98,5.66 81.98,6.34 81.82,6.49 81.47,6.49 81.33,6.35 v1(81.33,5.97)
  L3 w0.135: v1(81.33,5.97) 80.96,6.34 80.18,6.34 79.89,6.63 79.89,7.83 80.17,9.23 83.48,12.53 83.7,13.65 83.7,15.1 83.56,15.24 83.39,15.32 83.21,15.26 J3.A40
PE_CPU1_2C_RX_10_DP: length 18.3
  TOP w0.13: v1(81.33,6.99) 81.52,6.8 81.95,6.8 82.28,6.47 82.28,4.24 82.53,3.99 J1.88
  L3 w0.135: J3.A39 83.46,15.75 83.52,15.57 83.73,15.47 83.98,15.22 83.98,13.62 83.73,12.39 83.45,12.11 83.45,11.9 83.16,11.62 82.96,11.62 80.43,9.09 80.17,7.8 80.17,6.74 80.3,6.62 80.96,6.62 v1(81.33,6.99)
PE_CPU1_2C_RX_11_DN: length 19.1
  TOP w0.13: J1.84 84.13,3.99 84.38,4.24 84.38,4.92 84.2,5.09 84.2,5.48 84.38,5.66 84.38,6.34 84.22,6.49 83.87,6.49 83.73,6.35 v1(83.73,5.97)
  L3 w0.135: v1(83.73,5.97) 83.36,6.34 82.58,6.34 82.29,6.63 82.29,7.72 82.43,8.38 87.7,13.66 87.7,15.1 87.57,15.24 87.4,15.32 87.21,15.26 J3.A36
PE_CPU1_2C_RX_11_DP: length 19.1
  TOP w0.13: v1(83.73,6.99) 83.92,6.8 84.35,6.8 84.68,6.47 84.68,4.24 84.93,3.99 J1.82
  L3 w0.135: v1(83.73,6.99) 83.36,6.62 82.7,6.62 82.57,6.74 82.57,7.69 82.68,8.25 87.2,12.77 87.41,12.77 87.7,13.05 87.7,13.26 87.98,13.54 87.98,15.22 87.73,15.47 87.52,15.57 87.46,15.75 J3.A35
PE_CPU1_2C_TX_8_DN: length 19.8
  BOTTOM w0.13: J3.B45 77.45,19.79 77.28,19.85 77.12,19.76 76.99,19.64 76.99,16.48 75.99,14.48 75.99,13.35 76.07,12.97 76.28,12.83 76.35,12.45 76.21,12.24 76.29,11.86 76.5,11.72 76.57,11.34 76.44,11.14 76.6,10.34 77.45,9.48 78.28,5.34 78.28,4.24 78.53,3.99 J1.97
PE_CPU1_2C_TX_8_DP: length 19.8
  BOTTOM w0.13: J3.B46 77.2,20.29 77.14,20.12 77.14,20.12 76.94,20.01 76.69,19.77 76.69,16.55 75.69,14.55 75.69,13.32 76.09,11.33 76.31,10.19 77.17,9.33 77.98,5.31 77.98,4.24 77.73,3.99 J1.99
PE_CPU1_2C_TX_9_DN: length 19.4
  BOTTOM w0.13: J1.91 80.93,3.99 80.68,4.24 80.68,5.34 80,8.75 80.23,9.93 80.44,10.07 80.52,10.45 80.38,10.66 80.46,11.04 80.21,12.25 80.35,12.45 80.27,12.83 80.07,12.97 79.99,13.35 79.99,14.48 80.99,16.48 80.99,19.64 81.12,19.76 81.28,19.85 81.28,19.85 81.45,19.79 J3.B41
PE_CPU1_2C_TX_9_DP: length 19.4
  BOTTOM w0.13: J1.93 80.13,3.99 80.38,4.24 80.38,5.31 79.69,8.75 79.94,9.99 80.14,11.04 79.69,13.32 79.69,14.55 80.69,16.55 80.69,19.77 80.94,20.01 81.13,20.11 81.14,20.12 81.2,20.29 J3.B42
PE_CPU1_2C_TX_10_DN: length 19.5
  BOTTOM w0.13: J3.B37 85.45,19.8 85.27,19.86 85.11,19.78 84.99,19.66 84.99,16.48 83.99,14.48 83.99,13.86 83.92,13.48 84.05,13.27 83.98,12.89 83.77,12.75 83.7,12.37 83.83,12.16 83.76,11.78 83.55,11.65 82.64,7.07 83.08,4.85 83.08,4.24 83.33,3.99 J1.85
PE_CPU1_2C_TX_10_DP: length 19.5
  BOTTOM w0.13: J1.87 82.53,3.99 82.78,4.24 82.78,4.82 82.32,7.07 83.69,13.89 83.69,14.55 84.69,16.55 84.69,19.78 84.93,20.03 85.14,20.13 85.14,20.13 85.2,20.3 J3.B38
PE_CPU1_2C_TX_11_DN: length 20.3
  BOTTOM w0.13: J3.B33 89.45,19.8 89.27,19.86 89.11,19.77 88.99,19.65 88.99,16.48 87.99,14.48 87.99,13.32 87.74,12.05 87.46,11.77 87.46,11.53 87.19,11.25 86.94,11.25 86.67,10.98 86.67,10.73 86.39,10.45 86.14,10.45 85.51,9.82 85,7.25 85.48,4.85 85.48,4.24 85.73,3.99 J1.79
PE_CPU1_2C_TX_11_DP: length 20.3
  BOTTOM w0.13: J1.81 84.93,3.99 85.18,4.24 85.18,4.82 84.69,7.25 85.23,9.97 87.46,12.2 87.69,13.35 87.69,14.55 88.69,16.55 88.69,19.78 88.93,20.02 89.14,20.13 89.14,20.13 89.2,20.3 J3.B34
PE_CPU1_2D_RX_12_DN: length 22.4
  TOP w0.13: v1(86.13,5.97) 86.13,6.35 86.27,6.49 86.62,6.49 86.78,6.34 86.78,5.66 86.6,5.48 86.6,5.09 86.78,4.92 86.78,4.24 86.53,3.99 J1.78
  L3 w0.135: J3.A30 93.21,15.26 93.39,15.32 93.56,15.23 93.7,15.1 93.7,13.71 92.63,12.64 88.2,11.75 84.8,8.34 84.69,7.83 84.69,6.63 84.98,6.34 85.76,6.34 v1(86.13,5.97)
PE_CPU1_2D_RX_12_DP: length 22.4
  TOP w0.13: J1.76 87.33,3.99 87.08,4.24 87.08,6.47 86.75,6.8 86.32,6.8 v1(86.13,6.99)
  L3 w0.135: v1(86.13,6.99) 85.76,6.62 85.1,6.62 84.97,6.74 84.97,7.8 85.05,8.2 88.34,11.49 91.69,12.16 91.86,12.05 92.26,12.13 92.37,12.3 92.77,12.38 93.98,13.59 93.98,15.21 93.73,15.46 93.52,15.57 93.46,15.75 J3.A29
PE_CPU1_2D_RX_13_DN: length 24
  TOP w0.13: v1(88.53,5.97) 88.53,6.35 88.67,6.49 89.02,6.49 89.18,6.34 89.18,5.66 89,5.48 89,5.09 89.18,4.92 89.18,4.24 88.93,3.99 J1.72
  L3 w0.135: v1(88.53,5.97) 88.16,6.34 87.38,6.34 87.09,6.63 87.09,7.83 87.22,8.46 89.14,10.38 95.77,11.71 97.7,13.64 97.7,15.1 97.56,15.23 97.39,15.32 97.21,15.26 J3.A26
PE_CPU1_2D_RX_13_DP: length 24
  TOP w0.13: v1(88.53,6.99) 88.72,6.8 89.15,6.8 89.48,6.47 89.48,4.24 89.73,3.99 J1.70
  L3 w0.135: J3.A25 97.46,15.75 97.52,15.57 97.73,15.46 97.98,15.21 97.98,13.53 97.7,13.24 97.7,13.04 97.41,12.75 97.21,12.75 95.91,11.45 89.28,10.12 87.48,8.33 87.37,7.8 87.37,6.74 87.5,6.62 88.16,6.62 v1(88.53,6.99)
PE_CPU1_2D_RX_14_DN: length 18.7
  TOP w0.13: v1(98.13,6.99) 97.94,6.79 96.82,6.79 96.38,6.35 96.38,4.24 96.13,3.99 J1.62
  L3 w0.135: J3.A22 101.27,15.37 101.45,15.43 101.6,15.36 101.7,15.25 101.7,13.61 101.62,13.21 101.45,13.1 101.37,12.7 101.49,12.53 101.37,11.96 101.09,11.68 100.88,11.68 100.6,11.39 100.6,11.19 99.79,10.39 99.72,9.99 99.55,9.88 99.47,9.48 99.58,9.31 99.5,8.91 99.33,8.8 99.25,8.4 99.36,8.23 99.24,7.59 99.24,6.66 99.1,6.53 98.58,6.53 v1(98.13,6.99)
PE_CPU1_2D_RX_14_DP: length 18.7
  TOP w0.13: J1.60 96.93,3.99 96.68,4.24 96.68,4.63 96.86,4.8 96.86,5.19 96.68,5.36 96.68,6.22 96.95,6.49 97.99,6.49 98.13,6.35 v1(98.13,5.97)
  L3 w0.135: v1(98.13,5.97) 98.41,6.25 99.22,6.25 99.51,6.55 99.51,7.56 100.05,10.25 101.63,11.82 101.9,13.16 101.98,13.58 101.98,15.37 101.76,15.59 101.57,15.68 101.51,15.86 J3.A21
PE_CPU1_2D_RX_15_DN: length 19.2
  TOP w0.13: v1(100.53,6.99) 100.34,6.79 99.22,6.79 98.78,6.35 98.78,4.24 98.53,3.99 J1.56
  L3 w0.135: J3.A17 106.22,15.75 106.16,15.57 105.95,15.46 105.7,15.21 105.7,13.82 105.41,13.54 105.21,13.54 104.92,13.25 104.92,13.05 102.18,10.3 101.68,7.83 101.68,6.74 101.56,6.62 100.9,6.62 v1(100.53,6.99)
PE_CPU1_2D_RX_15_DP: length 19.2
  TOP w0.13: v1(100.53,5.97) 100.53,6.35 100.39,6.49 99.35,6.49 99.08,6.22 99.08,5.36 99.26,5.19 99.26,4.8 99.08,4.63 99.08,4.24 99.33,3.99 J1.54
  L3 w0.135: J3.A16 106.47,15.26 106.29,15.32 106.12,15.23 105.98,15.09 105.98,13.71 102.44,10.16 101.96,7.8 101.96,6.63 101.67,6.34 100.9,6.34 v1(100.53,5.97)
PE_CPU1_2D_TX_12_DN: length 22.8
  BOTTOM w0.13: J1.73 88.13,3.99 87.88,4.24 87.88,4.85 87.41,7.21 87.74,8.88 90.1,11.24 90.35,11.24 90.62,11.52 90.62,11.76 90.9,12.04 92.01,12.26 92.21,12.12 92.6,12.2 92.73,12.41 93.11,12.48 93.87,13.24 93.99,13.84 93.99,14.48 94.99,16.48 94.99,19.65 95.11,19.77 95.28,19.85 95.45,19.79 J3.B27
PE_CPU1_2D_TX_12_DP: length 22.8
  BOTTOM w0.13: J3.B28 95.2,20.3 95.14,20.12 95.14,20.12 94.93,20.02 94.69,19.77 94.69,16.55 93.69,14.55 93.69,13.87 93.59,13.39 92.96,12.76 90.75,12.32 87.46,9.03 87.1,7.21 87.58,4.82 87.58,4.24 87.33,3.99 J1.75
PE_CPU1_2D_TX_13_DN: length 24.1
  BOTTOM w0.13: J3.B23 99.45,19.79 99.28,19.85 99.11,19.77 98.99,19.65 98.99,16.48 97.99,14.48 97.99,13.84 97.85,13.14 97.58,12.86 97.58,12.62 97.3,12.34 97.05,12.34 96.13,11.42 95.75,11.34 95.61,11.13 95.23,11.06 95.02,11.2 92.39,10.67 90.07,8.34 89.82,7.13 90.28,4.85 90.28,4.24 90.53,3.99 J1.67
PE_CPU1_2D_TX_13_DP: length 24.1
  BOTTOM w0.13: J3.B24 99.2,20.3 99.14,20.12 99.14,20.12 98.93,20.02 98.69,19.77 98.69,16.55 97.69,14.55 97.69,13.87 97.57,13.29 95.98,11.7 92.24,10.95 89.78,8.49 89.51,7.13 89.98,4.82 89.98,4.24 89.73,3.99 J1.69
PE_CPU1_2D_TX_14_DN: length 21.2
  BOTTOM w0.13: J3.B19 103.45,19.79 103.28,19.85 103.12,19.76 102.99,19.64 102.99,16.48 101.99,14.48 101.99,13.89 101.82,13.04 101.55,12.77 101.55,12.52 101.27,12.24 101.03,12.24 100.75,11.97 100.75,11.72 100.48,11.45 100.23,11.45 97.28,8.5 97.01,7.17 97.48,4.85 97.48,4.24 97.73,3.99 J1.57
PE_CPU1_2D_TX_14_DP: length 21.3
  BOTTOM w0.13: J1.59 96.93,3.99 97.18,4.24 97.18,4.82 96.7,7.17 97,8.65 101.54,13.19 101.69,13.92 101.69,14.55 102.69,16.55 102.69,19.77 102.94,20.01 103.14,20.12 103.14,20.12 103.2,20.29 J3.B20
PE_CPU1_2D_TX_15_DN: length 24.1
  BOTTOM w0.13: J1.51 100.13,3.99 99.88,4.24 99.88,4.85 99.42,7.17 99.68,8.48 103.77,12.57 103.99,13.69 103.99,14.48 104.99,16.48 104.99,17.04 105.26,17.31 108.56,17.97 108.99,18.39 108.99,19.77 108.72,20.04 108.54,20.13 108.48,20.3 J3.B14
PE_CPU1_2D_TX_15_DP: length 24.1
  BOTTOM w0.13: J3.B15 108.23,19.8 108.41,19.86 108.54,19.79 108.69,19.64 108.69,18.52 108.41,18.25 105.11,17.59 104.69,17.16 104.69,16.55 103.69,14.55 103.69,13.72 103.49,12.72 103.21,12.45 102.96,12.45 102.69,12.17 102.69,11.92 102.42,11.65 102.17,11.65 101.89,11.37 101.89,11.13 99.4,8.63 99.1,7.17 99.58,4.82 99.58,4.24 99.33,3.99 J1.53
PWRBRK_J3_N: length 25.1
  TOP w0.114: U1.6 103.89,10.41 104.51,9.79 104.51,9 104.65,8.86 R99.1 105.16,8.44 104.08,7.37 102.36,7.37 100.71,9.02 99.57,9.02 95.76,12.83 95.76,14.86 94.87,15.74 94.87,18.52 94.8,18.59 94.8,19.5 94.11,20.19 93.66,20.19 J3.B30
PWRBRK_J4_N: length 53.1
  TOP w0.114: U1.4 102.59,10.38 102.23,10.03 R98.1 100.09,9.64 99.69,10.03 99.69,14.99 100.71,16 100.71,18.03 100.87,18.2 100.87,19.34 101.81,20.27 101.81,27.64 104.51,30.34 105.72,30.34 107.7,32.32 107.7,35.44 107.27,35.87 107.26,35.87 106.93,36.2 106.93,37.21 106.17,37.97 93.47,37.97 92.84,38.6 J4.B30
PWRBRK_SLOT4_N: length 19.8
  TOP w0.114: v1(106.05,12.19) 105.26,12.98 R74.2 104.42,12.98 104.27,12.83 U1.1 103.89,12.19 103.76,12.06 102.7,12.06 102.59,12.18 U1.3 ; v1(113.6,5.08) 113.6,4.63 112.93,3.96 J1.20
  L3 w0.137: v1(106.05,12.19) 110.24,8 112.65,8 113.15,7.5 113.15,5.78 113.16,5.78 113.16,5.52 v1(113.6,5.08)
RST_J3_N: length 2.5
  TOP w0.114: R26.2 110.26,8.53 110.49,8.77 U6.2 110.49,10.41 v1(110.49,10.41)
RST_J3_TRI_N: length 6.4
  TOP w0.114: U6.4 111.58,11.49 111.71,11.62 111.71,12.03 111.72,12.04 111.72,12.63 111.71,12.63 111.71,13.92 113.03,15.24 113.03,15.71 J3.A11
RST_J4_N: length 1.6
  TOP w0.114: R52.2 v1(111,30.61) 111.38,30.99 U7.2
RST_J4_TRI_N: length 4.3
  TOP w0.114: U7.4 112.03,34.43 113.84,36.24 J4.A11
RST_N: length 3.7
  TOP w0.114: R112.1 95.25,57.61 94.99,57.35 v1(94.99,56.21) U2.3
RST_P1_SLOT4_N: length 34.4
  TOP w0.114: v1(110.49,11.68) 110.49,11.18 110.24,10.92 109.22,10.92 108.93,10.64 108.93,7.91 109.12,7.72 R26.1 109.73,7.24 109.22,6.73 v1(108.71,6.73) ; v1(111.32,22.73) 111.32,25.08 110.74,25.65 110.74,27.18 111,27.43 R52.1
  L3 w0.137: v1(110.49,11.68) 111.7,11.68 111.89,11.87 111.89,13.97 113.54,15.62 114.17,15.62 114.63,16.08 114.63,19.57 113.67,20.54 113.67,20.95 111.89,22.73 v1(111.32,22.73)
  BOTTOM w0.114: J1.29 108.93,6.52 v1(108.71,6.73)
SLOT4_PRSNT_R_N: length 7.3
  TOP w0.114: R29.2 v1(37.32,8.86)
  BOTTOM w0.114: J1.199 37.73,4.56 37.55,4.74 37.55,8.63 v1(37.32,8.86)
SLOT4_WAKE_R_N: length 36.3
  TOP w0.114: v1(112.39,10.9) 112.08,10.9 111.95,10.77 111.95,8.06 111.61,7.72 R1.1 110.72,7.72 109.47,6.48 109.47,4.32 109.73,4.06 J1.28 ; v1(112.59,22.73) 112.59,24.32 111.25,25.65 111.25,27.05 111.44,27.24 111.44,29.88 113.28,31.72 R54.1
  L3 w0.137: v1(112.39,10.9) 112.39,13.84 113.79,15.24 114.43,15.24 115.06,15.88 115.06,19.72 114.05,20.73 114.05,21.27 v1(112.59,22.73)
SMB_0_ISO_SCL: length 22
  TOP w0.114: Q1.2 104.72,45.9 105.18,45.44 R102.1 R59.2 v1(106.15,44.3)
  L3 w0.137: v1(106.15,44.3) 106.82,43.62 116.91,43.62 117.98,42.55 117.98,40.89 118.62,40.26 118.92,40.26 J4.B5
SMB_0_ISO_SDA: length 16.2
  TOP w0.114: v1(109.7,44.3) R60.2 R103.1 108.74,45.44 108.28,45.9 Q2.2
  L3 w0.137: v1(109.7,44.3) 109.91,44.09 117.1,44.09 118.84,42.35 J4.B6
SMB_0_R_SCL: length 34.5
  TOP w0.114: v1(105.68,46.89) Q1.3 106.81,46.1 106.96,45.95 R59.1 ; R108.1 v1(93.22,60.58) R33.2
  L3 w0.137: v1(93.22,60.58) 93.47,60.83 93.47,61.37 93.91,61.81 98.87,61.81 104.61,56.07 104.61,46.4 105.16,45.85 106.91,45.85 107.23,46.17 107.23,46.7 107.04,46.89 v1(105.68,46.89)
SMB_0_R_SDA: length 34.5
  TOP w0.114: v1(109.23,46.89) Q2.3 110.24,46.1 110.52,45.82 R60.1 ; R109.1 v1(94.23,60.58) R32.2
  L3 w0.137: v1(109.23,46.89) 107.85,46.89 107.7,46.74 107.7,45.97 107.1,45.38 104.96,45.38 104.14,46.2 104.14,55.88 98.68,61.34 94.11,61.34 93.94,61.17 93.94,60.87 v1(94.23,60.58)
SMB_0_SCL: length 3.8
  TOP w0.114: R33.1 93.22,57.66 93.69,57.19 v1(93.69,56.21) U2.5
SMB_0_SDA: length 3.6
  TOP w0.114: R32.1 v1(94.23,57.78) 94.34,57.68 U2.4
SMB_1_ISO_SCL: length 21.8
  TOP w0.114: v1(106.15,23.98) R62.2 R101.1 105.18,25.12 104.72,25.58 Q4.2
  L3 w0.137: v1(106.15,23.98) 106.61,23.51 112.6,23.51 113.65,22.47 117.49,22.47 118.02,21.93 118.02,20.53 118.55,20 118.85,20 J3.B5
SMB_1_ISO_SDA: length 16.1
  TOP w0.114: v1(109.7,23.98) R61.2 R100.1 108.74,25.12 108.28,25.58 Q3.2
  L3 w0.137: v1(109.7,23.98) 112.8,23.98 113.84,22.94 117.68,22.94 118.84,21.78 J3.B6
SMB_1_R_SCL: length 58.6
  TOP w0.114: R62.1 106.96,25.25 106.43,25.78 Q4.3 105.68,28.33 106.43,29.08 v1(108.4,29.08) ; R106.1 v1(91.19,60.58) R35.2
  L3 w0.137: v1(108.4,29.08) 108.87,29.55 111.08,29.55 111.55,30.01 111.55,30.92 110.93,31.54 108.3,31.54 107.6,32.24 107.6,33.52 107.21,33.91 106.3,33.91 105.58,34.63 105.58,35.52 105.03,36.07 105.03,39.63 103.89,40.77 103.89,42.93 102.62,44.2 102.62,55.56 99.63,58.55 92.27,58.55 91.19,59.63 v1(91.19,60.58)
SMB_1_R_SDA: length 54.7
  TOP w0.114: R61.1 110.52,25.18 109.92,25.78 Q3.3 109.23,28.14 v1(110.18,29.08) ; R34.2 v1(92.2,60.58) R107.1
  L3 w0.137: v1(92.2,60.58) 92.2,59.28 92.46,59.01 99.82,59.01 103.08,55.75 103.08,44.39 106.05,41.43 106.05,40.64 106.79,39.89 106.79,36.59 107.7,35.69 107.7,34.09 108.07,33.71 108.07,32.43 108.49,32.01 111.12,32.01 112.01,31.11 112.01,29.82 111.28,29.08 v1(110.18,29.08)
SMB_1_SCL: length 4.1
  TOP w0.114: R35.1 91.19,57.78 92.39,56.58 v1(92.39,56.21) U2.7
SMB_1_SDA: length 3.9
  TOP w0.114: U2.6 93.04,56.95 v1(92.2,57.78) R34.1
SMB_2_SCL: length 4.5
  TOP w0.114: U2.9 v1(91.09,56.21) 89.51,57.78 89.28,57.78 89.15,57.91 R64.1
SMB_2_SDA: length 4.2
  TOP w0.114: R63.1 v1(90.17,57.78) 91.74,56.22 U2.8
SMB_3_SCL: length 5.3
  TOP w0.114: U2.11 v1(89.79,56.21) 89.1,56.9 88.01,56.9 87.12,57.78 R66.1
SMB_3_SDA: length 4.9
  TOP w0.114: R65.1 v1(88.14,57.78) 88.58,57.34 89.33,57.34 90.44,56.23 U2.10
SMB_3V3_CLK_P1: length 1.4
  TOP w0.114: R25.1 v1(107.85,12.26) R21.2
SMB_3V3_SCL: length 1.3
  TOP w0.114: R57.2 99.44,51.37 v1(99.57,51.5) 99.69,51.37 R23.1
SMB_3V3_SDA: length 1.3
  TOP w0.114: R19.2 99.44,50.36 v1(99.57,50.23) 99.69,50.36 R22.1
SMB_3V3_SDA_P1: length 1.4
  TOP w0.114: R24.1 v1(107.9,9.59) R20.2
SMB_4_SCL: length 3.8
  TOP w0.114: U2.14 89.79,47.5 v1(88.65,46.35) R68.1
SMB_4_SDA: length 3.9
  TOP w0.114: R67.1 87.63,46.17 v1(89.14,47.68) U2.13
SMB_5_SCL: length 3.5
  TOP w0.114: R70.1 v1(90.68,46.35) 90.81,46.49 90.81,47.33 90.81,47.33 90.81,47.36 91.09,47.63 U2.16
SMB_5_SDA: length 3.6
  TOP w0.114: R69.1 89.66,46.48 90.37,47.19 90.37,47.52 90.37,47.52 90.37,47.54 90.44,47.61 v1(90.44,47.68) U2.15
SMB_6_SCL: length 125.2
  TOP w0.114: R111.1 v1(92.71,46.35) 92.71,47.33 92.39,47.65 U2.18 ; R30.2 v1(80.26,44.27) ; R36.2 v1(87.22,27.39)
  L3 w0.137: v1(92.71,46.35) 91.43,45.07 86.55,45.07 85.06,46.57 81.62,46.57 80.04,45 80.04,44.49 v1(80.26,44.27)
  BOTTOM w0.114: v1(87.22,27.39) 86.85,27.02 86.51,27.02 86.36,27.17 86.36,27.68 85.46,28.57 42.92,28.57 36.96,34.54 36.96,40.64 38.68,42.37 79.19,42.37 79.96,43.13 79.96,43.97 v1(80.26,44.27)
SMB_6_SDA: length 127.7
  TOP w0.114: R110.1 91.69,46.23 92.2,46.74 92.2,47.21 v1(91.74,47.68) U2.17 ; R31.2 v1(79.25,44.27) ; R37.2 v1(87.22,26.37)
  L3 w0.137: v1(91.74,47.68) 92.19,47.23 92.19,46.5 91.24,45.54 86.75,45.54 85.25,47.04 81.42,47.04 79.58,45.19 79.58,44.6 v1(79.25,44.27)
  BOTTOM w0.114: v1(79.25,44.27) 79.51,44.01 79.51,43.32 79.01,42.82 38.5,42.82 36.51,40.83 36.51,34.36 42.74,28.13 85.28,28.13 85.92,27.5 85.92,26.99 86.32,26.58 87.01,26.58 v1(87.22,26.37)
SMB_7_SCL: length 3.7
  TOP w0.114: R72.1 v1(94.74,46.35) 94.74,46.57 93.69,47.63 U2.20
SMB_7_SDA: length 3.8
  TOP w0.114: R71.1 93.98,46 93.98,46.69 93.04,47.63 v1(93.04,47.68) U2.19
SMB_FRU_SCL: length 3.8
  TOP w0.114: R30.1 80.03,45.98 80.03,47.34 v1(80.52,47.83) U5.6
SMB_FRU_SDA: length 3.7
  TOP w0.114: R31.1 79.59,46.09 79.59,47.49 v1(79.25,47.83) U5.5
SMB_SENSOR_SCL: length 3.4
  TOP w0.114: U4.10 83.93,26.14 v1(85.18,27.39) R36.1
SMB_SENSOR_SDA: length 3.2
  TOP w0.114: U4.9 84.71,25.64 v1(85.18,26.11) 85.45,26.37 R37.1
SMB_SLOT4_3V3_CLK_R_P1: length 11.1
  TOP w0.114: J1.32 108.13,4.11 108.46,4.45 108.46,4.97 107.01,6.42 107.01,7.42 106.05,8.38 v1(106.05,10.29) 106.05,11.3 106.3,11.56 R21.1
SMB_SLOT4_3V3_R_SCL: length 82.3
  TOP w0.114: v1(103.63,22.99) 103.4,23.22 103.4,27.9 104.9,29.4 106.11,29.4 107.51,30.8 108.9,30.8 v1(109.6,30.1) ; U2.22 94.99,50.16 95.89,51.05 97.83,51.05 R57.1 v1(98.15,52.17)
  L3 w0.137: v1(98.15,52.17) 98.15,51.28 97.92,51.05 97.28,51.05 96.77,50.55 96.77,48.77 100.46,45.09 100.46,44.07 99.89,43.5 99.89,40.77 100.97,39.69 100.97,37.47 100.71,37.21 100.71,36.19 99.79,35.27 99.79,32.92 100.71,32 103.38,32 104.78,30.61 109.09,30.61 v1(109.6,30.1) ; v1(114.53,5.97) 114.53,7.52 113.06,8.99 111.22,8.99 108.8,11.4 108.8,13.17 109.6,13.97 109.6,14.33 110.77,15.49 110.77,16.68 109.54,17.91 107.31,17.91 106.68,18.54 106.68,19.56 105.92,20.32 105.92,21.21 105.16,21.97 104.14,21.97 103.53,22.58 103.53,22.89 v1(103.63,22.99)
  BOTTOM w0.114: J1.17 113.73,4 114.05,4.32 114.05,5.49 v1(114.53,5.97)
SMB_SLOT4_3V3_R_SDA: length 76.7
  TOP w0.114: v1(98.15,49.68) R19.1 97.89,50.61 96.07,50.61 95.64,50.18 U2.23 ; v1(110.24,30.73) 109.59,30.73 109.09,31.24 107.32,31.24 105.92,29.84 104.71,29.84 102.95,28.09 102.95,23.2 v1(102.74,22.99)
  L3 w0.137: v1(110.24,30.73) 109.9,31.07 104.97,31.07 103.76,32.28 103.76,35.31 103,36.07 103,38.7 102.62,39.08 102.62,40.01 101.73,40.89 101.73,43.18 100.92,43.98 100.92,45.28 97.24,48.96 97.24,50.35 97.48,50.59 98,50.59 98.15,50.44 v1(98.15,49.68) ; v1(102.74,22.99) 103,22.73 103,22.45 104.01,21.44 104.01,20.42 104.9,19.53 104.9,18.8 106.3,17.4 108.33,17.4 108.71,17.02 108.71,16 107.95,15.24 107.95,13.46 108.33,13.08 108.33,11.21 111.02,8.52 112.86,8.52 114.05,7.33 114.05,5.56 v1(114.53,5.08)
  BOTTOM w0.114: v1(114.53,5.08) J1.15
SMB_SLOT4_3V3_SDA_R_P1: length 7.3
  TOP w0.114: R20.1 107.09,7.98 107.46,7.61 107.46,6.72 v1(108.33,5.84) 108.93,5.25 J1.30
TDR_50_OHMS_L1: length 152.4
  TOP w0.114: -3.87,19.17 -3.87,169.32 TDR5.2
TDR_50_OHMS_L3: length 152.4
  L3 w0.137: TDR6.2 -3.87,166.52 -3.87,16.38
TDR_50_OHMS_L8: length 152.4
  BOTTOM w0.114: TDR8.2 -3.87,18.33 -3.87,168.47
TDR_85_OHMS_L1_DN: length 152.4
  TOP w0.13: 154.06,26.41 154.06,172.48 157,175.41 157,176.43 157.13,176.56 158.12,176.56
TDR_85_OHMS_L1_DP: length 152.4
  TOP w0.13: 153.76,26.41 153.76,172.61 156.69,175.54 156.69,176.43 156.56,176.56 TDR1.2
TDR_85_OHMS_L3_DN: length 152.4
  L3 w0.135: 158.12,170.97 157.12,170.97 156.98,170.83 156.98,169.81 154.05,166.88 154.05,20.83
TDR_85_OHMS_L3_DP: length 152.4
  L3 w0.135: TDR2.2 156.57,170.97 156.71,170.83 156.71,169.93 153.77,166.99 153.77,20.83
TDR_85_OHMS_L6_DN: length 152.4
  L6 w0.135: 153.77,174.87 153.77,28.71 156.71,25.78 156.71,24.87 156.57,24.74 TDR3.3
TDR_85_OHMS_L6_DP: length 152.4
  L6 w0.135: 154.05,174.87 154.05,28.83 156.98,25.9 156.98,24.87 157.12,24.74 TDR3.2
TDR_85_OHMS_L8_DN: length 152.4
  BOTTOM w0.13: 153.76,169.29 153.76,23.1 156.69,20.17 156.69,19.28 156.56,19.15 TDR4.3
TDR_85_OHMS_L8_DP: length 152.4
  BOTTOM w0.13: TDR4.2 157.13,19.15 157,19.28 157,20.29 154.06,23.23 154.06,169.29
THERM_N: length 4.3
  TOP w0.114: R104.1 85.79,23.82 85.55,23.57 v1(85.22,23.57) 84.84,23.95 84.84,24.38 84.58,24.64 U4.7
U2_A0: length 5.3
  TOP w0.114: R13.1 R15.2 v1(83.95,57.78) 83.95,57.28 83.06,56.39 U5.1
U2_A1: length 5
  TOP w0.114: R9.1 R10.2 v1(81.92,57.78) 81.92,56.64 81.79,56.52 U5.2
U2_A2: length 5.2
  TOP w0.114: U5.3 80.52,56.39 79.88,57.02 v1(79.88,57.78) R5.2 R4.1
U2_WP: length 4.7
  TOP w0.114: U5.7 v1(81.79,47.83) 82.3,47.32 R27.2 R17.1
U4_DN1: length 189.7
  TOP w0.114: v1(33.12,38.07) 33.67,38.62 33.67,46.96 50.32,63.61 129.13,63.61 142.85,49.9 143.92,49.9 144.15,50.13 144.15,50.42 143.84,50.72 C30.2 Q5.2 ; v1(74,24.08) 74.32,24.4 76.24,24.4 77.11,25.26 77.49,25.26 77.61,25.14 U4.3
  BOTTOM w0.114: v1(74,24.08) 73.7,24.38 44.98,24.38 33.63,35.74 33.63,37.57 v1(33.12,38.07)
U4_DN2: length 85.6
  TOP w0.114: Q6.2 C32.1 4.65,38.3 v1(4.42,38.07) ; v1(75.27,23.06) 75.59,23.38 76.51,23.38 77.35,24.22 77.53,24.22 77.61,24.14 U4.5
  BOTTOM w0.114: v1(75.27,23.06) 74.96,23.38 44.56,23.38 31.86,36.08 5.72,36.08 4.97,36.83 4.97,37.53 v1(4.42,38.07)
U4_DP1: length 189.7
  TOP w0.114: v1(34.39,38.07) 33.91,38.56 33.91,46.86 50.42,63.37 129.03,63.37 142.75,49.66 144.02,49.66 144.39,50.03 144.39,50.42 144.65,50.69 C30.1 144.65,51.44 144.79,51.57 Q5.3 145.75,53.15 Q5.1 ; v1(74,24.97) 74.33,24.64 76.14,24.64 77.01,25.5 77.49,25.5 77.62,25.64 U4.2
  BOTTOM w0.114: v1(34.39,38.07) 33.88,37.56 33.88,35.84 45.09,24.64 73.67,24.64 v1(74,24.97)
U4_DP2: length 85.7
  TOP w0.114: Q6.1 6.55,40.83 Q6.3 5.6,39.26 5.46,39.12 C32.2 5.46,38.3 v1(5.69,38.07) ; v1(75.27,23.95) 75.6,23.62 76.41,23.62 77.25,24.46 77.45,24.46 77.62,24.64 U4.4
  BOTTOM w0.114: v1(5.69,38.07) 5.21,37.59 5.21,36.93 5.82,36.32 31.96,36.32 44.66,23.62 74.94,23.62 v1(75.27,23.95)
WAKE_J4_N: length 6.6
  TOP w0.114: J4.B11 114.57,38.61 114.57,36.4 113.28,35.12 R54.2
WAKE_R_N: length 12.2
  TOP w0.114: R1.2 111.71,8.99 111.71,10.96 111.95,11.2 111.95,11.93 111.96,11.94 111.96,12.73 111.95,12.73 111.95,13.59 114.57,16.21 114.57,18.29 J3.B11

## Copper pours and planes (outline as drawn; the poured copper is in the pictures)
GND on TOP (solid shape): 6.95,21.87 12.25,16.58 6.95,11.28 3.26,11.28 3.22,11.47 3.14,11.66 3.03,11.84 2.9,11.99 2.72,12.13 2.63,12.19 2.41,12.28 2.22,12.33 2.1,12.34 1.92,12.35 1.64,12.4 1.4,12.5 1.25,12.6 0.99,12.88 0.88,13.06 0.81,13.28 0.77,13.48 0.77,21.87
GND on TOP (solid shape): outline of 144 points within 22.73,78.61 27.3,84.84
GND on TOP (solid shape): outline of 89 points within 111.63,27.56 139.83,30.61
GND on TOP (solid shape): outline of 221 points within 111.63,47.75 139.83,50.8
GND on BOTTOM (solid shape): outline of 144 points within 22.73,78.61 27.3,84.84
GND on L2_GND (solid shape): outline of 9225 points within 0.76,3.8 149.23,91.24
GND on L3 (solid shape): outline of 146 points within 22.73,78.61 27.3,84.84
GND on L4_PWR (solid shape): outline of 8934 points within 0.76,3.8 126.11,91.24
GND on L5_PWR (solid shape): outline of 8435 points within 0.76,3.8 113.03,91.24
GND on L7_GND (solid shape): outline of 9225 points within 0.76,3.8 149.23,91.24
